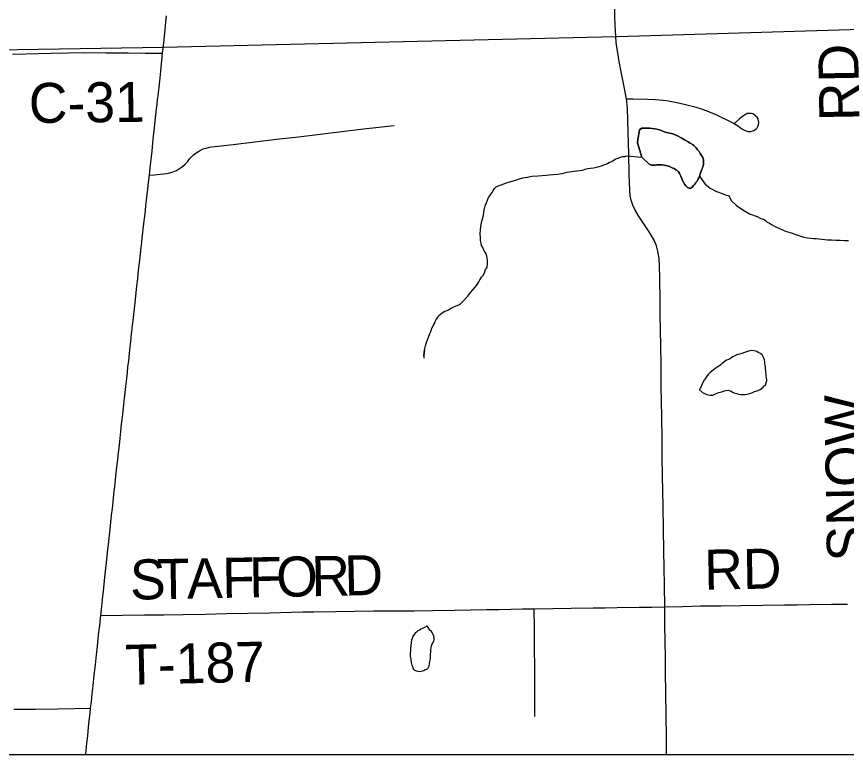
# Model space of a CAD drawing. Extents: x 103424 to 286016, y 38711 to 110967.
# Drawn here: x 142995 to 149253, y 38711 to 44275 of the extents above; entities that cross this region are included whole.
import ezdxf

# ---------------------------------------------------------------- set-up
doc = ezdxf.new("R2010")
doc.units = 0
for name, color, linetype in [('GM_X_Corporation', 7, 'Continuous'), ('GM_X_County_Road', 7, 'Continuous'), ('GM_X_County_Road_Text', 7, 'Continuous'), ('GM_X_Minor_Lake', 7, 'Continuous'), ('GM_X_Minor_River', 7, 'Continuous'), ('GM_X_State_Route', 7, 'Continuous'), ('GM_X_Township_Road', 7, 'Continuous'), ('GM_X_Township_Road_Text', 7, 'Continuous')]:
    doc.layers.add(name, color=color, linetype=linetype)

msp = doc.modelspace()

# ---------------------------------------------------------------- linework, layer by layer
at = {"layer": 'GM_X_Corporation'}
for points in [[(103423.7, 96534.8), (103423.7, 38711.2), (175679.7, 38711.2), (175679.7, 110967.2), (119699, 110967.2), (119716.9, 106542.5), (119719.8, 106322.8), (119720.8, 106006.3), (119709.7, 99445.7), (119706.4, 99064.2), (119663.9, 96690), (117026.4, 96688.2), (115542.1, 96665), (105081.7, 96574.5)], [(119963.5, 38711.2), (149532.9, 38711.2), (149528, 39851), (149476.1, 42604.7), (149451.3, 44180.8), (147524, 44122.7), (147511.7, 44122.4), (144100.1, 44042.4), (133604.6, 43873.3), (130307.3, 43800.5), (126993.8, 43728), (121865.1, 43580.2), (119934.2, 43543)]]:
    msp.add_lwpolyline(points, close=True, dxfattribs=at)
msp.add_lwpolyline([(149451.3, 44180.8), (147524, 44122.7), (147511.7, 44122.4), (144100.1, 44042.4), (133604.6, 43873.3), (130307.3, 43800.5), (126993.8, 43728), (121865.1, 43580.2), (119934.2, 43543), (119908.2, 46302.1), (119859.8, 51426.6), (119800.4, 57496.9), (119747.3, 63220.6), (119711.4, 67089.1)], dxfattribs=at)
at = {"layer": 'GM_X_County_Road'}
msp.add_lwpolyline([(142965.4, 43992.3), (143065.5, 43994.8), (143160.4, 43996.7), (143255.3, 43998.6), (143380.4, 44001.1), (143505.5, 44003.6), (143670.5, 44002.3), (143835.6, 44001), (143965.6, 44000), (144095.5, 43999)], dxfattribs=at)
at = {"layer": 'GM_X_Minor_Lake'}
for points in [[(148161.7, 43116.8), (148165.5, 43127), (148167.3, 43137.1), (148173.1, 43147.3), (148174.8, 43165.5), (148176.5, 43181.7), (148176.1, 43195.8), (148173.9, 43205.9), (148167.6, 43217.9), (148161.3, 43227.8), (148150.9, 43243.7), (148142.5, 43257.7), (148130.1, 43271.6), (148119.7, 43285.5), (148103.1, 43303.3), (148092.8, 43311.1), (148074.5, 43320.8), (148054, 43332.5), (148031.5, 43346.1), (148006.9, 43359.7), (147980.3, 43375.3), (147962, 43383), (147943.6, 43390.7), (147921.3, 43396.2), (147896.9, 43401.8), (147874.5, 43409.3), (147852.1, 43418.9), (147833.8, 43424.6), (147811.4, 43428.2), (147789.1, 43431.7), (147770.9, 43433.3), (147744.6, 43434.8), (147726.4, 43434.4), (147710.3, 43434), (147692.3, 43421.5), (147689, 43391.2), (147685.3, 43374.9), (147681.7, 43350.6), (147678.3, 43324.3), (147711.1, 43214.7)], [(147711.1, 43214.7), (147678.3, 43324.3), (147681.7, 43350.6), (147685.3, 43374.9), (147689, 43391.2), (147692.3, 43421.5), (147710.3, 43434), (147726.4, 43434.4), (147744.6, 43434.8), (147770.9, 43433.3), (147789.1, 43431.7), (147811.4, 43428.2), (147833.8, 43424.6), (147852.1, 43418.9), (147874.5, 43409.3), (147896.9, 43401.8), (147921.3, 43396.2), (147943.6, 43390.7), (147962, 43383), (147980.3, 43375.3), (148006.9, 43359.7), (148031.5, 43346.1), (148054, 43332.5), (148074.5, 43320.8), (148092.8, 43311.1), (148103.1, 43303.3), (148119.7, 43285.5), (148130.1, 43271.6), (148142.5, 43257.7), (148150.9, 43243.7), (148161.3, 43227.8), (148167.6, 43217.9), (148173.9, 43205.9), (148176.1, 43195.8), (148176.5, 43181.7), (148174.8, 43165.5), (148173.1, 43147.3), (148167.3, 43137.1), (148165.5, 43127), (148161.7, 43116.8), (148155.9, 43102.5), (148150.2, 43088.3), (148146.5, 43072), (148140.7, 43059.8), (148132.9, 43045.5), (148127, 43035.3), (148117.2, 43022.9), (148109.3, 43012.7), (148101.5, 43000.4), (148089.6, 42990), (148075.7, 42977.6), (148055.3, 42987.3), (148042.9, 42999.1), (148032.6, 43011), (148024.1, 43027), (148015.7, 43042.9), (148009.3, 43059), (148005, 43071), (148000.8, 43081), (147994.4, 43093), (147986.1, 43104.9), (147977.8, 43114.8), (147967.6, 43120.6), (147955.3, 43128.4), (147945.1, 43132.3), (147934.9, 43138.1), (147918.5, 43145.8), (147904.3, 43149.5), (147892.1, 43153.3), (147879.9, 43155.1), (147863.7, 43156.7), (147847.5, 43158.4), (147833.4, 43158.1), (147821.3, 43157.8), (147811.2, 43155.6), (147801.1, 43155.4), (147782.9, 43155), (147772.7, 43158.8), (147762.5, 43164.6), (147711.1, 43214.7)], [(147711.1, 43214.7), (147762.5, 43164.6), (147772.7, 43158.8), (147782.9, 43155), (147801.1, 43155.4), (147811.2, 43155.6), (147821.3, 43157.8), (147833.4, 43158.1), (147847.5, 43158.4), (147863.7, 43156.7), (147879.9, 43155.1), (147892.1, 43153.3), (147904.3, 43149.5), (147918.5, 43145.8), (147934.9, 43138.1), (147945.1, 43132.3), (147955.3, 43128.4), (147967.6, 43120.6), (147977.8, 43114.8), (147986.1, 43104.9), (147994.4, 43093), (148000.8, 43081), (148005, 43071), (148009.3, 43059), (148015.7, 43042.9), (148024.1, 43027), (148032.6, 43011), (148042.9, 42999.1), (148055.3, 42987.3), (148075.7, 42977.6), (148089.6, 42990), (148101.5, 43000.4), (148109.3, 43012.7), (148117.2, 43022.9), (148127, 43035.3), (148132.9, 43045.5), (148140.7, 43059.8), (148146.5, 43072), (148150.2, 43088.3), (148155.9, 43102.5), (148161.7, 43116.8)], [(148639.5, 41657.4), (148637.1, 41671.5), (148634.8, 41687.6), (148630.5, 41699.6), (148626.2, 41709.6), (148617.9, 41723.5), (148605.5, 41735.4), (148589.1, 41743.1), (148578.9, 41748.9), (148566.7, 41752.7), (148554.5, 41754.5), (148538.3, 41756.1), (148528.3, 41753.9), (148514.2, 41751.6), (148500.1, 41747.2), (148484.1, 41740.8), (148466, 41734.4), (148447.9, 41729.9), (148427.9, 41723.4), (148411.8, 41717), (148397.9, 41708.6), (148381.9, 41700.2), (148365.9, 41689.8), (148349.9, 41683.4), (148330, 41668.8), (148318.1, 41660.5), (148306.2, 41650.1), (148292.2, 41639.7), (148276.3, 41629.3), (148260.3, 41618.8), (148226.6, 41591.9), (148212.7, 41577.4), (148202.8, 41567.1), (148195, 41554.8), (148187.1, 41544.5), (148181.3, 41534.3), (148175.4, 41528.1), (148175.4, 41526.1), (148146.5, 41460.9)], [(148146.5, 41460.9), (148167.1, 41441.2), (148187.6, 41429.5), (148208, 41421.8), (148226.2, 41420.2), (148246.4, 41420.7), (148266.4, 41429.2), (148290.4, 41439.8), (148314.6, 41446.4), (148332.6, 41452.8), (148346.7, 41455.2), (148362.8, 41457.5), (148383.2, 41449.9), (148395.4, 41444.1), (148411.8, 41436.4), (148428, 41432.7), (148440.2, 41428.9), (148456.5, 41425.2), (148470.6, 41425.6), (148486.8, 41425.9), (148504.9, 41428.3), (148523, 41432.7), (148541.1, 41437.2), (148559.1, 41447.7), (148587.2, 41456.4), (148603.2, 41462.8), (148625.1, 41479.4), (148633, 41489.7), (148642.9, 41495.9), (148652.3, 41530.5), (148651.8, 41552.7), (148649.5, 41564.7), (148649.3, 41576.8), (148646.9, 41595), (148646.7, 41605), (148644.4, 41615.1), (148644, 41633.3), (148641.7, 41647.3), (148639.5, 41657.4), (148637.1, 41671.5), (148634.8, 41687.6), (148630.5, 41699.6), (148626.2, 41709.6), (148617.9, 41723.5), (148605.5, 41735.4), (148589.1, 41743.1), (148578.9, 41748.9), (148566.7, 41752.7), (148554.5, 41754.5), (148538.3, 41756.1), (148528.3, 41753.9), (148514.2, 41751.6), (148500.1, 41747.2), (148484.1, 41740.8), (148466, 41734.4), (148447.9, 41729.9), (148427.9, 41723.4), (148411.8, 41717), (148397.9, 41708.6), (148381.9, 41700.2), (148365.9, 41689.8), (148349.9, 41683.4), (148330, 41668.8), (148318.1, 41660.5), (148306.2, 41650.1), (148292.2, 41639.7), (148276.3, 41629.3), (148260.3, 41618.8), (148226.6, 41591.9), (148212.7, 41577.4), (148202.8, 41567.1), (148195, 41554.8), (148187.1, 41544.5), (148181.3, 41534.3), (148175.4, 41528.1), (148175.4, 41526.1), (148146.5, 41460.9)], [(148146.5, 41460.9), (148167.1, 41441.2), (148187.6, 41429.5), (148208, 41421.8), (148226.2, 41420.2), (148246.4, 41420.7), (148266.4, 41429.2), (148290.4, 41439.8), (148314.6, 41446.4), (148332.6, 41452.8), (148346.7, 41455.2), (148362.8, 41457.5), (148383.2, 41449.9), (148395.4, 41444.1), (148411.8, 41436.4), (148428, 41432.7), (148440.2, 41428.9), (148456.5, 41425.2), (148470.6, 41425.6), (148486.8, 41425.9), (148504.9, 41428.3), (148523, 41432.7), (148541.1, 41437.2), (148559.1, 41447.7), (148587.2, 41456.4), (148603.2, 41462.8), (148625.1, 41479.4), (148633, 41489.7), (148642.9, 41495.9), (148652.3, 41530.5), (148651.8, 41552.7), (148649.5, 41564.7), (148649.3, 41576.8), (148646.9, 41595), (148646.7, 41605), (148644.4, 41615.1), (148644, 41633.3), (148641.7, 41647.3), (148639.5, 41657.4)], [(146090.7, 39679.7), (146088.7, 39677.7), (146070.7, 39667.2), (146056.7, 39660.8), (146042.7, 39654.4), (146032.7, 39648.2), (146020.8, 39641.9), (146010.8, 39633.6), (146000.9, 39625.3), (145993, 39615), (145981.3, 39598.6), (145977.5, 39586.4), (145973.7, 39572.2), (145970.1, 39553.9), (145968.5, 39531.7), (145967, 39509.4), (145965.4, 39489.2), (145963.7, 39475), (145963.9, 39465), (145964.2, 39452.8), (145968.8, 39426.7), (145971.2, 39404.6), (145975.7, 39384.4), (145980, 39374.4), (145986.4, 39356.4), (145996.7, 39346.5), (146011, 39340.8), (146021.2, 39339)], [(146090.7, 39679.7), (146088.7, 39677.7), (146070.7, 39667.2), (146056.7, 39660.8), (146042.7, 39654.4), (146032.7, 39648.2), (146020.8, 39641.9), (146010.8, 39633.6), (146000.9, 39625.3), (145993, 39615), (145981.3, 39598.6), (145977.5, 39586.4), (145973.7, 39572.2), (145970.1, 39553.9), (145968.5, 39531.7), (145967, 39509.4), (145965.4, 39489.2), (145963.7, 39475), (145963.9, 39465), (145964.2, 39452.8), (145968.8, 39426.7), (145971.2, 39404.6), (145975.7, 39384.4), (145980, 39374.4), (145986.4, 39356.4), (145996.7, 39346.5), (146011, 39340.8), (146021.2, 39339), (146031.3, 39337.2), (146047.4, 39339.6), (146065.5, 39344), (146075.5, 39350.3), (146085.5, 39354.5), (146095.5, 39358.8), (146107.2, 39379.2), (146108.9, 39393.4), (146112.6, 39411.7), (146114.4, 39421.8), (146116.1, 39436), (146117.9, 39448.1), (146117.6, 39462.2), (146119.1, 39486.5), (146118.8, 39498.6), (146124.2, 39529), (146129.9, 39545.3), (146135.8, 39555.5), (146141.6, 39565.7), (146143.4, 39575.9), (146143.2, 39586), (146140.8, 39602.1), (146136.5, 39616.1), (146130.1, 39630.1), (146121.8, 39642), (146111.6, 39647.9), (146090.7, 39679.7)], [(146021.2, 39339), (146031.3, 39337.2), (146047.4, 39339.6), (146065.5, 39344), (146075.5, 39350.3), (146085.5, 39354.5), (146095.5, 39358.8), (146107.2, 39379.2), (146108.9, 39393.4), (146112.6, 39411.7), (146114.4, 39421.8), (146116.1, 39436), (146117.9, 39448.1), (146117.6, 39462.2), (146119.1, 39486.5), (146118.8, 39498.6), (146124.2, 39529), (146129.9, 39545.3), (146135.8, 39555.5), (146141.6, 39565.7), (146143.4, 39575.9), (146143.2, 39586), (146140.8, 39602.1), (146136.5, 39616.1), (146130.1, 39630.1), (146121.8, 39642), (146111.6, 39647.9), (146090.7, 39679.7)]]:
    msp.add_lwpolyline(points, dxfattribs=at)
at = {"layer": 'GM_X_Minor_River'}
for points in [[(146067.8, 41698.3), (146070.5, 41762.9), (146067.5, 41716.4), (146070.5, 41762.9), (146077.9, 41793.4), (146085.5, 41817.8), (146097, 41846.3), (146108.4, 41878.9), (146122, 41907.4), (146127.7, 41925.7), (146139.3, 41948.2), (146147.1, 41960.5), (146152.9, 41974.7), (146158.6, 41991), (146170.5, 42003.4), (146180.2, 42021.8), (146204, 42040.4), (146224, 42053), (146242, 42059.4), (146252, 42063.7), (146268, 42074.1), (146288, 42082.7), (146310, 42093.2), (146330.1, 42101.7), (146344.1, 42108.1), (146355.9, 42120.5), (146399.4, 42165.8), (146421, 42196.6), (146438.7, 42217.2), (146452.5, 42233.6), (146464.4, 42248), (146474.2, 42262.3), (146482, 42274.6), (146489.7, 42291), (146501.4, 42309.4), (146511.3, 42319.7), (146525, 42342.2), (146532.5, 42368.6), (146544.3, 42383), (146547.7, 42413.4), (146547.2, 42437.6), (146544.8, 42453.7), (146540.5, 42469.7), (146536.1, 42485.8), (146529.8, 42497.8), (146521.4, 42509.7), (146513, 42527.7), (146502.4, 42549.7), (146498, 42565.7), (146493.5, 42587.8), (146493, 42612.1), (146492.5, 42634.3), (146493.7, 42670.6), (146499, 42707.1), (146504.6, 42731.4), (146510.2, 42749.7), (146515.7, 42776.1), (146519.2, 42802.4), (146524.8, 42826.8), (146530.3, 42849.1), (146538, 42871.5), (146545.6, 42891.8), (146555.3, 42910.2), (146563.1, 42922.5), (146571, 42934.8), (146580.8, 42949.1), (146588.5, 42963.4), (146600.4, 42977.8), (146612.2, 42990.2), (146622.2, 42996.5), (146696.4, 43024.3), (146722.5, 43030.9), (146750.6, 43039.6), (146780.7, 43050.4), (146812.8, 43059.2), (146847.1, 43063.9), (146881.3, 43070.7), (146927.7, 43073.8), (146958, 43076.4), (146986.2, 43079.1), (147012.5, 43081.7), (147040.7, 43084.3), (147073, 43087), (147109.2, 43091.9), (147147.5, 43100.8), (147183.7, 43107.6), (147217.9, 43112.4), (147242.1, 43114.9), (147258.3, 43117.3), (147270.3, 43119.6), (147284.4, 43123.9), (147302.5, 43128.4), (147324.7, 43130.9), (147346.8, 43135.4), (147368.9, 43139.9), (147389, 43144.4), (147407.1, 43148.8), (147425.1, 43157.3), (147447.2, 43165.8), (147467.2, 43176.4), (147483.2, 43182.8)], [(147483.2, 43182.8), (147495.2, 43189.1), (147515.1, 43201.6), (147531.2, 43208), (147549.2, 43214.5), (147567.3, 43218.9), (147581.4, 43221.3), (147593.5, 43225.6), (147711.1, 43214.7)], [(148146.5, 43072), (148188.2, 43010.4), (148225.2, 42980.9), (148274.2, 42955.7), (148317, 42940.5), (148347.6, 42929), (148365.8, 42925.4), (148384.8, 42887.5), (148424, 42850), (148473.2, 42818.7), (148522.4, 42787.5), (148579.4, 42766.5), (148608, 42753), (148628.3, 42747.4), (148642.7, 42737.6), (148657.1, 42725.8), (148673.4, 42718.1), (148687.8, 42708.3), (148706.2, 42696.6), (148726.6, 42686.9), (148793.9, 42658.1), (148818.4, 42650.6), (148844.8, 42641.1), (148873.3, 42631.6), (148901.8, 42622.1), (148932.3, 42612.7), (148960.8, 42607.2), (148985.1, 42603.7), (149005.3, 42602.2), (149025.6, 42600.6), (149045.8, 42599), (149070.1, 42595.5), (149110.6, 42592.3), (149141, 42591), (149173.3, 42589.7), (149205.7, 42588.4), (149238.1, 42587), (149268.4, 42587.7)]]:
    msp.add_lwpolyline(points, dxfattribs=at)
at = {"layer": 'GM_X_State_Route'}
for points in [[(144095.5, 43999), (144104.9, 44076.2), (144115.7, 44175.4), (144121, 44234.7), (144126.1, 44280.8)], [(143629.9, 39759.1), (143634.9, 39803.4), (143640.5, 39854.2), (143645.9, 39904.8), (143650, 39942.5), (143655.8, 39996), (143661.4, 40047.5), (143666.2, 40092.5), (143673.1, 40156.5), (143678.9, 40209.7), (143684, 40257.1), (143690.1, 40313), (143695.6, 40363.7), (143700.6, 40409.8), (143706.4, 40463.3), (143711.8, 40514.1), (143717.4, 40565.5), (143722.7, 40614), (143725.8, 40642), (143729.5, 40675.8), (143735.5, 40730.5), (143741.4, 40783.5), (143746.7, 40831.4), (143751.9, 40879.1), (143757.8, 40931.9), (143763.7, 40986), (143770.1, 41043.5), (143775.8, 41095.5), (143781.4, 41146.1), (143787.4, 41200.4), (143793.5, 41255.1), (143798.7, 41302), (143803.7, 41348.1), (143809.1, 41396.4), (143813.9, 41440.1), (143818.9, 41485.3), (143825.7, 41547.1), (143830.5, 41590.7), (143835.2, 41632.9), (143840.5, 41680.4), (143846.6, 41735.8), (143852, 41784.8), (143856.3, 41823.9), (143862.7, 41881.7), (143866.7, 41917.5), (143867.9, 41928.5), (143873.9, 41983), (143878.8, 42027.8), (143883.7, 42071.8), (143891.4, 42141.4), (143897.2, 42194.2), (143902.6, 42243.1), (143908.5, 42296.3), (143912.8, 42335.1), (143918.2, 42384.2), (143924.1, 42437.6), (143929.5, 42486.7), (143934.6, 42532.8), (143939.1, 42572.8), (143942.8, 42606.9), (143947.3, 42645.5), (143950.2, 42673.4), (143954.4, 42710), (143957.8, 42738.1), (143961.3, 42768.3), (143966.6, 42813.3), (143971, 42850.9), (143977, 42909.8), (143979.9, 42937.4), (143983.7, 42971.2), (143987.3, 43002.7), (143991.8, 43042.4), (143996.3, 43080.5), (144002.2, 43134.4), (144006.8, 43176.5), (144012.1, 43218.1), (144016.5, 43259.7), (144019.8, 43292.3), (144023, 43323), (144025.5, 43348.8), (144030.9, 43396.8), (144034.9, 43434.1), (144041.3, 43489.8), (144046.3, 43533.9), (144051.2, 43579.4), (144054.7, 43613.5), (144058.4, 43646.3), (144062, 43678.8), (144074.2, 43788.3), (144082.5, 43864.3), (144095.5, 43999)], [(143553.6, 39059), (143559.3, 39109.8), (143565.2, 39167.7), (143571.4, 39228.6), (143580.6, 39307.7), (143589.2, 39386.9), (143597.6, 39461.9), (143604.6, 39526.8), (143611, 39585.6), (143616.2, 39633.7), (143621.8, 39685.9), (143629.9, 39759.1)], [(143516.1, 38711.2), (143519.3, 38741), (143525.4, 38797), (143531.2, 38851.5), (143538.3, 38917.2), (143543.3, 38963.8), (143549.7, 39022.8), (143553.6, 39059)]]:
    msp.add_lwpolyline(points, dxfattribs=at)
at = {"layer": 'GM_X_Township_Road'}
for points in [[(147517.3, 44080.7), (147513.6, 44127.3), (147508.4, 44205.8), (147506.7, 44286), (147505.5, 44441.4), (147504.1, 44540), (147502.7, 44638.7), (147500.6, 44750.6), (147498.6, 44862.4), (147497.1, 45017.5), (147495.6, 45172.5), (147496.4, 45323.8), (147496.8, 45401.5)], [(147883.6, 39823.5), (147880.8, 39988.6), (147878.7, 40117.7), (147876.6, 40246.8), (147873.8, 40411.8), (147871, 40576.9), (147869, 40695.2), (147867, 40813.4), (147865.2, 40952), (147863.5, 41090.6), (147860.9, 41255.7), (147859.1, 41372.1), (147857.3, 41488.5), (147855.2, 41653.6), (147853.5, 41784.4), (147851.9, 41915.3), (147849.8, 42027.2), (147847.7, 42139.1), (147846, 42301.4), (147844.7, 42397.2), (147841.4, 42450.9), (147831.6, 42506), (147821.1, 42547.4), (147804.7, 42589.3), (147766, 42653), (147684.7, 42771.7), (147657.7, 42819.5), (147642.7, 42853), (147629.7, 42891.8), (147623.6, 42927.1), (147620.4, 42964.9), (147615.8, 43087.7), (147612.6, 43238.5), (147607.4, 43403.5), (147604.6, 43494.2), (147601.8, 43584.9), (147595.9, 43654.9), (147574.9, 43757.5), (147556.9, 43847.2), (147538.8, 43937), (147528.6, 44001.8), (147522.1, 44043.6), (147517.3, 44080.7)], [(147595.9, 43654.9), (147644.8, 43655.5), (147756.9, 43653.2), (147812.9, 43650.2), (147871.2, 43645), (147911.6, 43639), (147949, 43633), (148020, 43618.1), (148100.7, 43597.2), (148153, 43581.5), (148213.6, 43558.3), (148268.9, 43535.9), (148315.2, 43515), (148357.8, 43494), (148401.2, 43471.6), (148438.5, 43449.2), (148465.4, 43429.8), (148482.9, 43419.7), (148497.6, 43413.3), (148510.3, 43409.5), (148522.3, 43408.8), (148531.8, 43409.8), (148545.4, 43412.6), (148555, 43416.6), (148564.1, 43421.5), (148572.3, 43429), (148580.6, 43437.2), (148584.7, 43446.1), (148589.5, 43458.9), (148591.8, 43475.3), (148591, 43489.5), (148588, 43503), (148579.8, 43515.7), (148573.4, 43522.7), (148564.9, 43531.4), (148555.2, 43536.8), (148546.9, 43541.1), (148535, 43544.1), (148520.8, 43545.6), (148512.6, 43544.8), (148504.3, 43543.3), (148496.7, 43539.9), (148484.1, 43532.9), (148471.1, 43522.8), (148447.5, 43503.7), (148413.2, 43470.4)], [(143996.3, 43080.5), (144033.9, 43083), (144055.7, 43085), (144074.4, 43086.4), (144102.1, 43089.7), (144125, 43092.4), (144150.3, 43097), (144176, 43104.8), (144200.4, 43115.3), (144223.6, 43128.4), (144245.2, 43143.8), (144265.4, 43161.4), (144283.3, 43181), (144299.9, 43202.4), (144308.9, 43212.7), (144318.5, 43222.5), (144328.6, 43231.8), (144339.1, 43240.6), (144350.2, 43248.6), (144361.6, 43256.2), (144373.6, 43263.1), (144398.3, 43274.9), (144411.2, 43279.7), (144424.3, 43283.9), (144451, 43290), (144464.5, 43292), (144628.5, 43311.4), (144792.4, 43330.7), (144956.4, 43350.1), (145120.3, 43369.4), (145284.2, 43388.7), (145448.1, 43408.1), (145612, 43427.5), (145727.1, 43441.1), (145842.3, 43454.7)], [(143629.9, 39759.1), (143794.9, 39760.9), (143960, 39762.8), (144105.6, 39764.4), (144251.3, 39766), (144416.4, 39769.6), (144577.9, 39773), (144739.5, 39776.5), (144904.5, 39779.9), (145069.5, 39783.4), (145153.2, 39785.1), (145236.9, 39786.9), (145402, 39789), (145544.4, 39790.9), (145686.8, 39792.7), (145851.8, 39794), (145991.9, 39795.1), (146132, 39796.2), (146297, 39799), (146418, 39801.1), (146539, 39803.1), (146631.1, 39804.9), (146723.3, 39806.6), (146811.5, 39807.8), (146899.6, 39808.9), (147038.7, 39811.2), (147177.8, 39813.6), (147342.9, 39815.9), (147433.7, 39817.2), (147524.5, 39818.5), (147689.6, 39820.8), (147786.6, 39822.2), (147883.6, 39823.5), (148018.8, 39827.2), (148154.1, 39830.8), (148305.6, 39832.3), (148457.1, 39833.8), (148622.2, 39836.3), (148787.2, 39838.8), (148881.1, 39840.2), (148975, 39841.6), (149140.1, 39843.3), (149262.4, 39844.7)], [(146904.8, 38997.2), (146904.1, 39092.9), (146903.5, 39188.6), (146902.5, 39353.6), (146901.4, 39518.7), (146900.5, 39663.8), (146899.6, 39808.9)], [(147897.2, 38711.2), (147896.8, 38752), (147895.7, 38841.5), (147893.7, 39006.6), (147891.7, 39171.6), (147889.7, 39336.7), (147888.4, 39448.1), (147887, 39559.5), (147885.3, 39691.5), (147883.6, 39823.5)], [(143553.6, 39059), (143559.3, 39109.8), (143565.2, 39167.7), (143571.4, 39228.6), (143580.6, 39307.7), (143589.2, 39386.9), (143597.6, 39461.9), (143604.6, 39526.8), (143611, 39585.6), (143616.2, 39633.7), (143621.8, 39685.9), (143629.9, 39759.1)], [(142973.6, 39051.2), (143138.7, 39053.4), (143303.7, 39055.6), (143428.6, 39057.3), (143553.6, 39059)]]:
    msp.add_lwpolyline(points, dxfattribs=at)

# ---------------------------------------------------------------- texts
at = {"layer": 'GM_X_County_Road_Text'}
msp.add_text('C-31', height=301.87, rotation=0.67144, dxfattribs=at).set_placement((143088.8, 43471.8))
at = {"layer": 'GM_X_Township_Road_Text'}
for s, height, rotation, p in [('RD', 301.87, 90.98722, (149351.7, 43489.4)), ('SNOW', 301.87, 90.93574, (149409.2, 40169)), ('RD', 301.87, 0.99248, (148183.4, 39953.1)), ('S', 301.9, 1.07868, (143853.2, 39877.9)), ('T', 301.9, 1.07575, (144056.8, 39881.7)), ('A', 301.9, 1.07959, (144282.6, 39886)), ('F', 301.9, 1.07863, (144548.2, 39891)), ('F', 301.9, 1.07863, (144751.8, 39894.8)), ('O', 301.9, 1.07831, (144955.4, 39898.6)), ('R', 301.9, 1.07996, (145221.1, 39903.6)), ('D', 301.9, 1.4198, (145470.9, 39908.4)), ('T-187', 301.87, 1.39829, (143817.6, 39235.3))]:
    msp.add_text(s, height=height, rotation=rotation, dxfattribs=at).set_placement(p)

doc.saveas('drawing.dxf')
